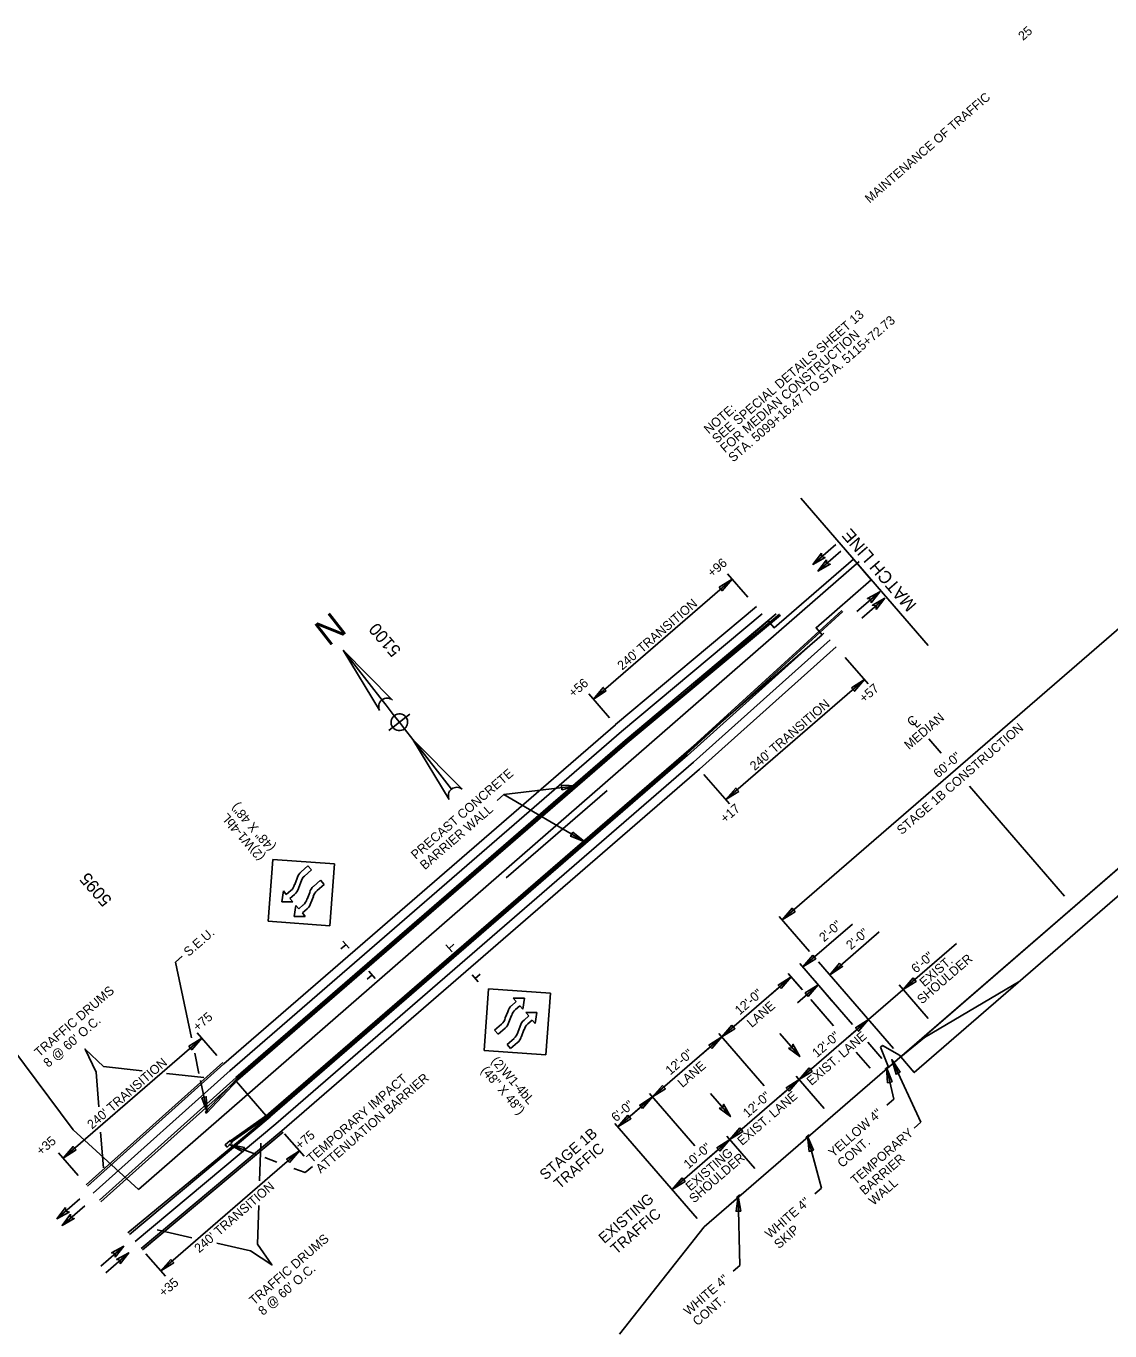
# Model space of a CAD drawing. Extents: x 259983 to 267998, y 211467 to 219827.
# Drawn here: x 261028 to 262447, y 218119 to 219827 of the extents above; entities that cross this region are included whole.
import ezdxf

# ---------------------------------------------------------------- set-up
doc = ezdxf.new("R2010")
doc.units = 0
for name, color, linetype in [('1', 7, 'Continuous'), ('CL', 7, 'Continuous'), ('Default', 7, 'Continuous'), ('DRAINAGE ARROWS', 7, 'Continuous'), ('Level 1', 7, 'Continuous'), ('Level 43', 7, 'Continuous'), ('Level 58', 7, 'Continuous'), ('R-W - CofA', 7, 'Continuous'), ('R_Border Notes', 7, 'Continuous'), ('R_MOT', 7, 'Continuous'), ('R_MOT STAGE 1', 7, 'Continuous'), ('R_MOT STAGE 2', 7, 'Continuous'), ('STATIONING1', 7, 'Continuous')]:
    doc.layers.add(name, color=color, linetype=linetype)

msp = doc.modelspace()

# ---------------------------------------------------------------- linework, layer by layer
at = {"layer": '1'}
for p, q in [((262471.6, 219049.6), (262018, 218656.9)), ((261653.7, 218820.8), (261759.5, 218758.9)), ((262053.9, 218615.4), (262014.1, 218661.4)), ((262109.8, 218651.5), (262044.9, 218595.3)), ((262145.1, 218641.3), (262080.2, 218585.1)), ((262131, 218526.4), (262246.1, 218626)), ((261232.6, 218609.3), (261223.7, 218601.6)), ((261223.7, 218601.6), (261244.6, 218502.7)), ((262092.9, 218539.8), (262040.9, 218599.8)), ((262132.9, 218524.2), (262065.6, 218601.9)), ((262029.7, 218582.2), (261939, 218503.7)), ((262002.5, 218558.6), (262029.7, 218582.2)), ((262002.5, 218558.6), (262029.7, 218582.2)), ((262043.1, 218566.8), (262025.8, 218586.7)), ((262044.5, 218565.2), (262025.8, 218586.7)), ((262037.8, 218548.4), (262065, 218572)), ((262083.1, 218551.1), (262061.1, 218576.5)), ((262208.9, 218528), (262171, 218571.9)), ((262085.1, 218518.3), (262055.3, 218552.7)), ((262085.1, 218518.3), (262060.3, 218546.9)), ((262109.9, 218520.1), (262092.9, 218539.8)), ((262163.6, 218488.7), (262127.1, 218530.9)), ((262131, 218526.4), (262040.3, 218447.8)), ((262103.8, 218502.8), (262131, 218526.4)), ((261939, 218503.7), (261848.3, 218425.1)), ((261911.8, 218480.1), (261939, 218503.7)), ((261994.3, 218439.8), (261935.1, 218508.2)), ((262148.5, 218475.6), (262130.1, 218496.9)), ((261248.9, 218482.4), (261254.5, 218455.8)), ((262133.3, 218462.6), (262115, 218483.8)), ((262164, 218422.2), (262154.7, 218463.5)), ((262199.6, 218392), (262161.5, 218474.1)), ((261256.4, 218446.6), (261265.1, 218405.3)), ((262040.3, 218447.8), (261949.5, 218369.3)), ((262013, 218424.3), (262040.3, 218447.8)), ((262072.9, 218410.2), (262036.3, 218452.4)), ((261903.6, 218361.2), (261844.4, 218429.7)), ((261848.3, 218425.1), (261802.9, 218385.8)), ((261821.1, 218401.6), (261848.3, 218425.1)), ((262155.1, 218414.5), (262164, 218422.2)), ((261906.5, 218266.2), (261799, 218390.4)), ((262190.7, 218384.3), (262199.6, 218392)), ((261330, 218349.7), (261294.3, 218363)), ((261949.5, 218369.3), (261873.9, 218303.8)), ((261922.3, 218345.7), (261949.5, 218369.3)), ((261982.1, 218331.6), (261945.6, 218373.8)), ((262069.5, 218305.9), (262051, 218373.8)), ((261356.6, 218339.8), (261340.8, 218345.7)), ((261393.6, 218326.1), (261378.7, 218331.6)), ((261402.9, 218334.1), (261393.6, 218326.1)), ((261962.4, 218204.6), (261960.3, 218295.2)), ((262060.6, 218298.3), (262069.5, 218305.9)), ((261953.6, 218196.9), (261962.4, 218204.6))]:
    msp.add_line(p, q, dxfattribs=at)
for points in [[(261935.3, 219092.3), (261952.3, 219103), (261939.2, 219087.8)], [(261787.7, 218956.6), (261770.8, 218945.9), (261783.8, 218961.1)], [(262108.7, 218960.7), (262125.7, 218971.4), (262112.7, 218956.2)], [(261729, 218833.2), (261749, 218832.5), (261729.7, 218827.3)], [(261961.2, 218825), (261944.2, 218814.3), (261957.3, 218829.5)], [(261744, 218771.5), (261759.5, 218758.9), (261740.9, 218766.3)], [(262034.9, 218667.6), (262018, 218656.9), (262031, 218672.1)], [(262057.9, 218610.5), (262044.9, 218595.3), (262061.8, 218606)], [(262093.2, 218600.3), (262080.2, 218585.1), (262097.1, 218595.8)], [(262016.7, 218567), (262029.7, 218582.2), (262012.8, 218571.5)], [(262016.7, 218567), (262029.7, 218582.2), (262012.8, 218571.5)], [(262189.3, 218580.9), (262176.3, 218565.7), (262193.3, 218576.3)], [(262052, 218556.8), (262065, 218572), (262048.1, 218561.3)], [(261952, 218518.9), (261939, 218503.7), (261956, 218514.4)], [(262118, 218511.2), (262131, 218526.4), (262114, 218515.7)], [(262114, 218515.7), (262131, 218526.4), (262118, 218511.2)], [(261241.2, 218491.4), (261258.1, 218502.1), (261245.1, 218486.8)], [(261926, 218488.4), (261939, 218503.7), (261922.1, 218493)], [(262053.3, 218463.1), (262040.3, 218447.8), (262057.2, 218458.5)], [(262161.8, 218444.8), (262154.7, 218463.5), (262155.9, 218443.6)], [(262172.4, 218457.4), (262161.5, 218474.1), (262167, 218454.8)], [(262027.2, 218432.6), (262040.3, 218447.8), (262023.3, 218437.2)], [(261861.3, 218440.3), (261848.3, 218425.1), (261865.2, 218435.8)], [(261258.1, 218424), (261265.1, 218405.3), (261263.9, 218425.3)], [(261835.3, 218409.9), (261848.3, 218425.1), (261831.4, 218414.4)], [(261815.9, 218401.1), (261802.9, 218385.8), (261819.9, 218396.5)], [(261962.5, 218384.5), (261949.5, 218369.3), (261966.5, 218380)], [(261093.6, 218355.7), (261076.7, 218345), (261089.7, 218360.2)], [(261311.8, 218353.3), (261294.3, 218363), (261313.9, 218358.9)], [(261936.5, 218354.1), (261949.5, 218369.3), (261932.6, 218358.6)], [(262058.9, 218355.4), (262051, 218373.8), (262053.1, 218353.8)], [(261373, 218339.1), (261386, 218354.4), (261369.1, 218343.6)], [(261886.9, 218319.1), (261873.9, 218303.8), (261890.9, 218314.5)], [(261963.7, 218275.5), (261960.3, 218295.2), (261957.7, 218275.4)], [(261217.6, 218212.5), (261204.6, 218197.3), (261221.5, 218208)]]:
    msp.add_lwpolyline(points, close=True, dxfattribs=at)
for points in [[(261644.7, 218813.1), (261653.7, 218820.8), (261749, 218832.5)], [(261123.2, 218412.2), (261119.7, 218457.4), (261105.4, 218487.8), (261129.6, 218465.1), (261180.1, 218459.5)], [(261212.1, 218456), (261260.9, 218450.6)], [(261129.3, 218332.4), (261125.7, 218379.1)], [(261333.8, 218315.4), (261335.5, 218364.5)], [(261277.8, 218233.7), (261321.9, 218223.8), (261350, 218205.2), (261331, 218232.4), (261332.8, 218283.2)], [(261199.6, 218251.2), (261245.3, 218240.9)]]:
    msp.add_lwpolyline(points, dxfattribs=at)
at = {"layer": 'CL'}
for p, q in [((262226, 218875), (262209.8, 218893.7)), ((262387.7, 218688.1), (262263.3, 218831.9))]:
    msp.add_line(p, q, dxfattribs=at)
at = {"layer": 'Default'}
for p, q in [((262173.1, 218477.7), (262883.8, 219093)), ((262626.7, 218870.5), (261916, 218255.2)), ((262190.9, 218457.1), (262644.6, 218849.9)), ((262204.3, 218503.1), (262329.2, 218576.8)), ((262173.1, 218477.7), (262204.3, 218503.1)), ((262149.5, 218492.5), (262146.7, 218490.2)), ((262156.3, 218466.5), (262146.7, 218490.2)), ((262171.5, 218479.6), (262149.5, 218492.5)), ((262173.1, 218477.7), (262171.5, 218479.6)), ((262158, 218464.7), (262156.3, 218466.5)), ((262173.1, 218477.7), (262190.9, 218457.1)), ((261916, 218255.2), (261805, 218114.8))]:
    msp.add_line(p, q, dxfattribs=at)
for points in [[(262156.9, 218465.4), (262153, 218462.1), (262153.9, 218461.1), (262157.8, 218464.5)], [(262053.2, 218375.7), (262049.3, 218372.3), (262050.2, 218371.3), (262054, 218374.7)], [(261962.5, 218297.1), (261958.6, 218293.8), (261959.5, 218292.8), (261963.3, 218296.1)]]:
    msp.add_lwpolyline(points, close=True, dxfattribs=at)
at = {"layer": 'Level 1'}
for p, q in [((261443.1, 219009.9), (261508, 218944.6)), ((261490.8, 218931.2), (261443.1, 219009.9)), ((261443.1, 219009.9), (261494.1, 218944.7)), ((261499.4, 218937.9), (261494.1, 218944.7)), ((261499.4, 218937.9), (261510.1, 218924.1)), ((261510.1, 218924.1), (261516.8, 218915.5)), ((261516.8, 218915.5), (261525.4, 218922.2)), ((261525.4, 218922.2), (261530.6, 218926.3)), ((261525.4, 218922.2), (261525.4, 218922.2)), ((261507.9, 218908.6), (261503.1, 218904.8)), ((261516.8, 218915.5), (261508.5, 218909.1)), ((261516.8, 218915.5), (261523.5, 218907)), ((261523.5, 218907), (261516.8, 218915.5)), ((261523.5, 218907), (261534.3, 218893.2)), ((261534.3, 218893.2), (261582, 218814.5)), ((261585.2, 218828.1), (261534.3, 218893.2)), ((261534.3, 218893.2), (261599.1, 218827.9))]:
    msp.add_line(p, q, dxfattribs=at)
for centre, radius, start, end in [((261500.9, 218935.9), 11.2, 128, 205.3196), ((261500.9, 218935.9), 11.2, 50.6804, 128), ((261516.8, 218915.6), 10.9, 128, 218), ((261516.8, 218915.6), 10.9, 38, 128), ((261516.8, 218915.6), 10.9, 308, 38), ((261516.8, 218915.6), 10.9, 218, 308), ((261592.1, 218819.3), 11.2, 128, 205.3196), ((261592.1, 218819.3), 11.2, 50.6804, 128)]:
    msp.add_arc(centre, radius, start, end, dxfattribs=at)
at = {"layer": 'Level 43'}
for points in [[(262058.1, 219122.2), (262088.2, 219148.2)], [(262064.7, 219113.5), (262094.7, 219139.5)], [(262145.6, 219086.5), (262115.6, 219060.5)], [(262152.2, 219077.8), (262122.1, 219051.8)], [(262040.9, 218477.9), (262015, 218508)], [(261950.2, 218399.4), (261924.2, 218429.5)], [(261068.6, 218265.6), (261098.7, 218291.6)], [(261075.2, 218256.9), (261105.2, 218282.8)], [(261156.1, 218229.8), (261126, 218203.8)], [(261162.6, 218221.1), (261132.6, 218195.1)]]:
    msp.add_lwpolyline(points, dxfattribs=at)
at = {"layer": 'Level 58'}
for points in [[(262069.3, 219136.8), (262058.1, 219122.2), (262074.2, 219131.2), (262069.5, 219132)], [(262075.9, 219128.1), (262064.7, 219113.5), (262080.8, 219122.4), (262076.1, 219123.3)], [(262134.4, 219071.9), (262145.6, 219086.5), (262129.5, 219077.5), (262134.2, 219076.7)], [(262141, 219063.1), (262152.2, 219077.8), (262136.1, 219068.8), (262140.8, 219067.9)], [(262026.3, 218489.1), (262040.9, 218477.9), (262032, 218494), (262031.1, 218489.3)], [(261935.6, 218410.6), (261950.2, 218399.4), (261941.2, 218415.5), (261940.4, 218410.8)], [(261079.8, 218280.2), (261068.6, 218265.6), (261084.7, 218274.5), (261080, 218275.4)], [(261086.4, 218271.5), (261075.2, 218256.9), (261091.3, 218265.8), (261086.5, 218266.7)], [(261144.9, 218215.2), (261156.1, 218229.8), (261140, 218220.9), (261144.7, 218220)], [(261151.5, 218206.5), (261162.6, 218221.1), (261146.6, 218212.2), (261151.3, 218211.3)]]:
    msp.add_lwpolyline(points, close=True, dxfattribs=at)
at = {"layer": 'R-W - CofA'}
for points in [[(261175.5, 218304.1), (262118.9, 219126.1)], [(260940.1, 218539), (260969.8, 218509.5), (261009.5, 218489.8), (261089.9, 218382.1), (261175.5, 218304.1)]]:
    msp.add_lwpolyline(points, dxfattribs=at)
at = {"layer": 'R_MOT'}
for p, q in [((261351, 218735.8), (261345.2, 218655.1)), ((261431.8, 218730.1), (261351, 218735.8)), ((261388.1, 218719.7), (261397.2, 218727.5)), ((261392.8, 218714.3), (261401.9, 218722.2)), ((261397.2, 218727.5), (261401.9, 218722.2)), ((261431.8, 218730.1), (261426, 218649.3)), ((261379.8, 218703), (261383.2, 218711.7)), ((261384.6, 218698.1), (261387.9, 218706.3)), ((261404.4, 218700.8), (261413.5, 218708.7)), ((261409.1, 218695.4), (261418.2, 218703.3)), ((261413.5, 218708.7), (261418.2, 218703.3)), ((261365, 218694.7), (261362.8, 218680.3)), ((261365, 218694.7), (261368.8, 218690.2)), ((261368.8, 218690.2), (261374.6, 218695.2)), ((261373.5, 218684.8), (261379.7, 218690.2)), ((261373.5, 218684.8), (261377.4, 218680.4)), ((261396.1, 218684.2), (261399.5, 218692.8)), ((261400.9, 218679.3), (261404.2, 218687.4)), ((261362.8, 218680.3), (261377.4, 218680.4)), ((261381.3, 218675.9), (261379.1, 218661.4)), ((261381.3, 218675.9), (261385.2, 218671.4)), ((261385.2, 218671.4), (261390.9, 218676.4)), ((261389.8, 218666), (261396, 218671.3)), ((261345.2, 218655.1), (261425.9, 218649.2)), ((261379.1, 218661.4), (261393.7, 218661.5)), ((261389.8, 218666), (261393.7, 218661.5)), ((261446.8, 218624.4), (261440.4, 218618.9)), ((261442.9, 218629), (261450.9, 218619.8)), ((261585.8, 218615), (261577.8, 218624.3)), ((261581.8, 218619.6), (261588.3, 218625.2)), ((261481, 218585), (261474.5, 218579.4)), ((261477, 218589.6), (261485, 218580.3)), ((261620, 218575.6), (261612, 218584.8)), ((261616, 218580.2), (261622.4, 218585.8)), ((261627.9, 218485.9), (261633.6, 218566.7)), ((261714.5, 218560.9), (261633.7, 218566.7)), ((261669.8, 218549.9), (261663.7, 218544.6)), ((261680.5, 218554.5), (261665.9, 218554.4)), ((261669.8, 218549.9), (261665.9, 218554.4)), ((261678.4, 218540.1), (261680.5, 218554.5)), ((261708.6, 218480.1), (261714.5, 218560.9)), ((261658.7, 218536.7), (261655.5, 218528.5)), ((261663.6, 218531.8), (261660.1, 218523.1)), ((261674.5, 218544.6), (261668.7, 218539.6)), ((261678.4, 218540.1), (261674.5, 218544.6)), ((261686.1, 218531.1), (261680, 218525.8)), ((261696.9, 218535.7), (261682.3, 218535.6)), ((261686.1, 218531.1), (261682.3, 218535.6)), ((261694.7, 218521.2), (261696.9, 218535.7)), ((261650.6, 218520.5), (261641.5, 218512.6)), ((261646.1, 218507.2), (261641.5, 218512.6)), ((261655.2, 218515.1), (261646.1, 218507.2)), ((261675, 218517.8), (261671.8, 218509.6)), ((261679.9, 218512.9), (261676.5, 218504.3)), ((261690.8, 218525.7), (261685.1, 218520.7)), ((261694.7, 218521.2), (261690.8, 218525.7)), ((261666.9, 218501.7), (261657.8, 218493.8)), ((261671.6, 218496.3), (261662.4, 218488.4)), ((261627.9, 218485.9), (261708.6, 218480.1)), ((261662.4, 218488.4), (261657.8, 218493.8))]:
    msp.add_line(p, q, dxfattribs=at)
for centre, major_axis in [((261399.4, 218706), (-11.6, 13.4)), ((261363.3, 218708.8), (11.6, -13.4)), ((261404.1, 218700.6), (-11.6, 13.4)), ((261415.7, 218687.2), (-11.6, 13.4)), ((261368.3, 218703.8), (11.6, -13.4)), ((261379.6, 218690), (11.6, -13.4)), ((261420.4, 218681.7), (-11.6, 13.4)), ((261384.7, 218685), (11.6, -13.4)), ((261675, 218531), (-11.6, 13.4)), ((261680.1, 218525.9), (-11.6, 13.4)), ((261639.2, 218534.2), (11.6, -13.4)), ((261643.9, 218528.8), (11.6, -13.4)), ((261691.3, 218512.1), (-11.6, 13.4)), ((261696.4, 218507.1), (-11.6, 13.4)), ((261655.5, 218515.4), (11.6, -13.4)), ((261660.2, 218509.9), (11.6, -13.4))]:
    msp.add_ellipse(centre, major_axis=major_axis, ratio=0.9, start_param=6.26006, end_param=6.849246, dxfattribs=at)
at = {"layer": 'R_MOT STAGE 1'}
for p, q in [((262209.2, 219015.9), (262042.3, 219208.8)), ((261799.8, 218912.5), (261984.4, 219067)), ((261891.3, 218875.3), (262096.1, 219061.9)), ((261892.7, 218873.8), (262097.5, 219060.4)), ((261991.6, 219057.3), (261807.5, 218903.3)), ((261815.2, 218894), (262010.3, 219057.7)), ((261816.5, 218892.5), (262014.4, 219057.2)), ((261817.8, 218891), (262015.7, 219055.7)), ((261893.8, 218872.2), (262072.7, 219032.3)), ((261901.9, 218863.3), (262080.7, 219023.4)), ((261909.9, 218854.3), (262088.7, 219014.4)), ((261287.1, 218468.6), (261799.6, 218912.3)), ((261807.5, 218903.3), (261294.9, 218459.5)), ((261302.8, 218450.5), (261815.3, 218894.2)), ((261304.1, 218448.9), (261816.7, 218892.7)), ((261305.4, 218447.4), (261818, 218891.2)), ((261344.7, 218402.1), (261891.4, 218875.3)), ((261346, 218400.6), (261892.7, 218873.8)), ((261347.3, 218399), (261894, 218872.3)), ((261355.2, 218390), (261901.9, 218863.3)), ((261363, 218380.9), (261909.7, 218854.2)), ((261656.7, 218711.9), (261789, 218826.4)), ((261106.9, 218310.1), (261285.6, 218470.4)), ((261108.4, 218308.3), (261287.1, 218468.6)), ((261295.1, 218459.7), (261116.1, 218299.2)), ((261124.1, 218290.2), (261303.1, 218450.7)), ((261126.1, 218287.9), (261304.8, 218448.1)), ((261262.7, 218405.2), (261304, 218448.8)), ((261264.2, 218403.8), (261305.4, 218447.4)), ((261305.4, 218447.4), (261304, 218448.8)), ((261304.1, 218448.9), (261305.4, 218447.4)), ((261161.3, 218247.2), (261346.5, 218399.9)), ((261347.5, 218399.2), (261163.4, 218245.1)), ((261264.2, 218403.8), (261262.7, 218405.2)), ((261295.6, 218367.5), (261344.7, 218402.1)), ((261296.8, 218365.9), (261345.8, 218400.4)), ((261344.7, 218402.1), (261345.8, 218400.4)), ((261344.7, 218402.1), (261346, 218400.6)), ((261171.1, 218235.9), (261355.2, 218390)), ((261362.9, 218380.8), (261178.8, 218226.7)), ((261180.6, 218225), (261364.7, 218379)), ((261296.8, 218365.9), (261295.6, 218367.5))]:
    msp.add_line(p, q, dxfattribs=at)
msp.add_lwpolyline([(261295.1, 218367.9), (261288.7, 218362.4), (261291.2, 218359.6), (261297.5, 218365)], close=True, dxfattribs=at)
at = {"layer": 'R_MOT STAGE 2'}
for p, q in [((261952.3, 219103), (261770.8, 218945.9)), ((261972.9, 219079.2), (261946.3, 219109.9)), ((262130.5, 218965.8), (262100.6, 219000.4)), ((262125.7, 218971.4), (261944.2, 218814.3)), ((261792.1, 218921.3), (261764.8, 218952.8)), ((261949.1, 218808.7), (261915.6, 218847.4)), ((261258.1, 218502.1), (261076.7, 218345)), ((261277.8, 218479.4), (261252.2, 218508.9)), ((261366.4, 218377), (261392, 218347.5)), ((261096.3, 218322.3), (261070.7, 218351.9)), ((261386, 218354.4), (261204.6, 218197.3)), ((261184.9, 218219.9), (261210.5, 218190.4))]:
    msp.add_line(p, q, dxfattribs=at)
for points in [[(261303.3, 218445.6), (261342.6, 218400.3), (262070.1, 219030.1), (262062.3, 219039.2), (262134.5, 219102.2), (262111.2, 219129.1), (262007.3, 219039.2), (261999.4, 219048.2)], [(262173.1, 218477.7), (262190.9, 218457.1), (262644.6, 218849.9), (262626.7, 218870.5)]]:
    msp.add_lwpolyline(points, close=True, dxfattribs=at)

# ---------------------------------------------------------------- texts
at = {"layer": '1'}
for s, height, rotation, p in [("240' TRANSITION", 12, 40.8733, (261808.6, 218983.2)), ("240' TRANSITION", 12, 40.8733, (261982, 218851.6)), ('MEDIAN', 12, 40.8733, (262184.1, 218879.1)), ('C', 12, 40.8733, (262187.8, 218909.1)), ('STAGE 1B CONSTRUCTION', 12, 40.8833, (262174.4, 218767.7)), ('L', 12, 40.8733, (262193.6, 218907.2)), ('60\'-0"', 12, 40.8833, (262222.3, 218841.9)), ('PRECAST CONCRETE', 12, 40.8833, (261538.4, 218735.4)), ('BARRIER WALL', 12, 40.8833, (261550.2, 218721.8)), ('2\'-0"', 12, 40.8833, (262072.7, 218627.3)), ('S.E.U.', 12, 40.8733, (261240.9, 218608.3)), ('2\'-0"', 12, 40.8933, (262108, 218617.1)), ('6\'-0"', 12, 40.8833, (262193.2, 218586.4)), ('SHOULDER', 12, 40.8833, (262200.9, 218546)), ('EXIST.', 12, 40.8833, (262204.1, 218568.6)), ('TRAFFIC DRUMS', 12, 40.8745, (261045.5, 218476.8)), ('12\'-0"', 12, 40.8833, (261962.4, 218531.8)), ('LANE', 12, 40.8833, (261978.2, 218515.2)), ("8 @ 60' O.C.", 12, 40.8745, (261057.2, 218463.1)), ('EXIST. LANE', 12, 40.8833, (262056.3, 218439.4)), ('12\'-0"', 12, 40.8833, (262063.6, 218476)), ('12\'-0"', 12, 40.8833, (261871.6, 218453.2)), ("240' TRANSITION", 12, 40.8733, (261114.5, 218382.3)), ('LANE', 12, 40.8833, (261887.4, 218436.7)), ('TEMPORARY IMPACT', 12, 40.8733, (261402.1, 218338.1)), ('ATTENUATION BARRIER', 12, 40.8733, (261413.8, 218324.5)), ('EXIST. LANE', 12, 40.8833, (261965.6, 218360.9)), ('12\'-0"', 12, 40.8833, (261972.9, 218397.4)), ('6\'-0"', 12, 40.8833, (261800.6, 218391.8)), ('YELLOW 4"', 12, 40.8833, (262084.8, 218345.5)), ('STAGE 1B', 14, 40.8733, (261707.9, 218315.5)), ('TEMPORARY', 12, 40.8833, (262114, 218309.7)), ('TRAFFIC', 14, 40.8733, (261726.6, 218303.9)), ('10\'-0"', 12, 40.8833, (261895.3, 218330.3)), ('CONT.', 12, 40.8833, (262096.6, 218331.9)), ('EXISTING', 12, 40.8833, (261897.9, 218301.3)), ('SHOULDER', 12, 40.8833, (261902.6, 218285.5)), ('BARRIER', 12, 40.8833, (262125.8, 218296.1)), ("240' TRANSITION", 12, 40.8933, (261254.8, 218220.3)), ('WALL', 12, 40.8833, (262137.5, 218282.5)), ('EXISTING', 14, 40.8733, (261785.1, 218232.5)), ('WHITE 4"', 12, 40.8833, (262001.9, 218239.3)), ('TRAFFIC', 14, 40.8733, (261800.8, 218218.3)), ('SKIP', 12, 40.8833, (262013.7, 218225.7)), ('TRAFFIC DRUMS', 12, 40.8921, (261326.6, 218152)), ("8 @ 60' O.C.", 12, 40.8921, (261338.4, 218138.4)), ('WHITE 4"', 12, 40.8833, (261895.3, 218138.3)), ('CONT.', 12, 40.8833, (261907.1, 218124.7))]:
    msp.add_text(s, height=height, rotation=rotation, dxfattribs=at).set_placement(p)
at = {"layer": 'DRAINAGE ARROWS'}
for s, p in [('SEE SPECIAL DETAILS SHEET 13', (261932.5, 219280)), ('STA. 5099+16.47 TO STA. 5115+72.73', (261953.8, 219255.4)), ('FOR MEDIAN CONSTRUCTION', (261943.2, 219267.7)), ('NOTE:', (261921.9, 219292.3))]:
    msp.add_text(s, height=12, rotation=40.8833, dxfattribs=at).set_placement(p)
at = {"layer": 'Level 1'}
for s, height, rotation, p in [('MAINTENANCE OF TRAFFIC', 11.7, 40.8733, (262132.5, 219594.5)), ('N', 34.2, 38, (261423.9, 219014))]:
    msp.add_text(s, height=height, rotation=rotation, dxfattribs=at).set_placement(p)
at = {"layer": 'R_Border Notes'}
msp.add_text('25', height=11.78, rotation=40.8833, dxfattribs=at).set_placement((262333.3, 219807.3))
at = {"layer": 'R_MOT'}
for s, rotation, p in [('(48" X 48")', 130.8833, (261355.1, 218752.7)), ('(2)W1-4bL', 130.8833, (261341.5, 218740.3)), ('(48" X 48")', 310.8833, (261622.8, 218459.3)), ('(2)W1-4bL', 310.8833, (261636.4, 218471.8))]:
    msp.add_text(s, height=12, rotation=rotation, dxfattribs=at).set_placement(p)
at = {"layer": 'R_MOT STAGE 2'}
for s, p in [('+96', (261926.4, 219104.6)), ('+56', (261744.7, 218947.3)), ('+57', (262125.2, 218940.4)), ('+17', (261943.4, 218783)), ('+75', (261252.9, 218510.3)), ('+75', (261386.8, 218355.6)), ('+35', (261047.9, 218348)), ('+35', (261208.4, 218162.7))]:
    msp.add_text(s, height=12, rotation=40.8821, dxfattribs=at).set_placement(p)
at = {"layer": 'STATIONING1'}
for s, p in [('MATCH LINE', (262194.9, 219069.5)), ('5100', (261520, 219010.1)), ('5095', (261141.5, 218683.3))]:
    msp.add_text(s, height=16.5, rotation=130.8833, dxfattribs=at).set_placement(p)

doc.saveas('drawing.dxf')
